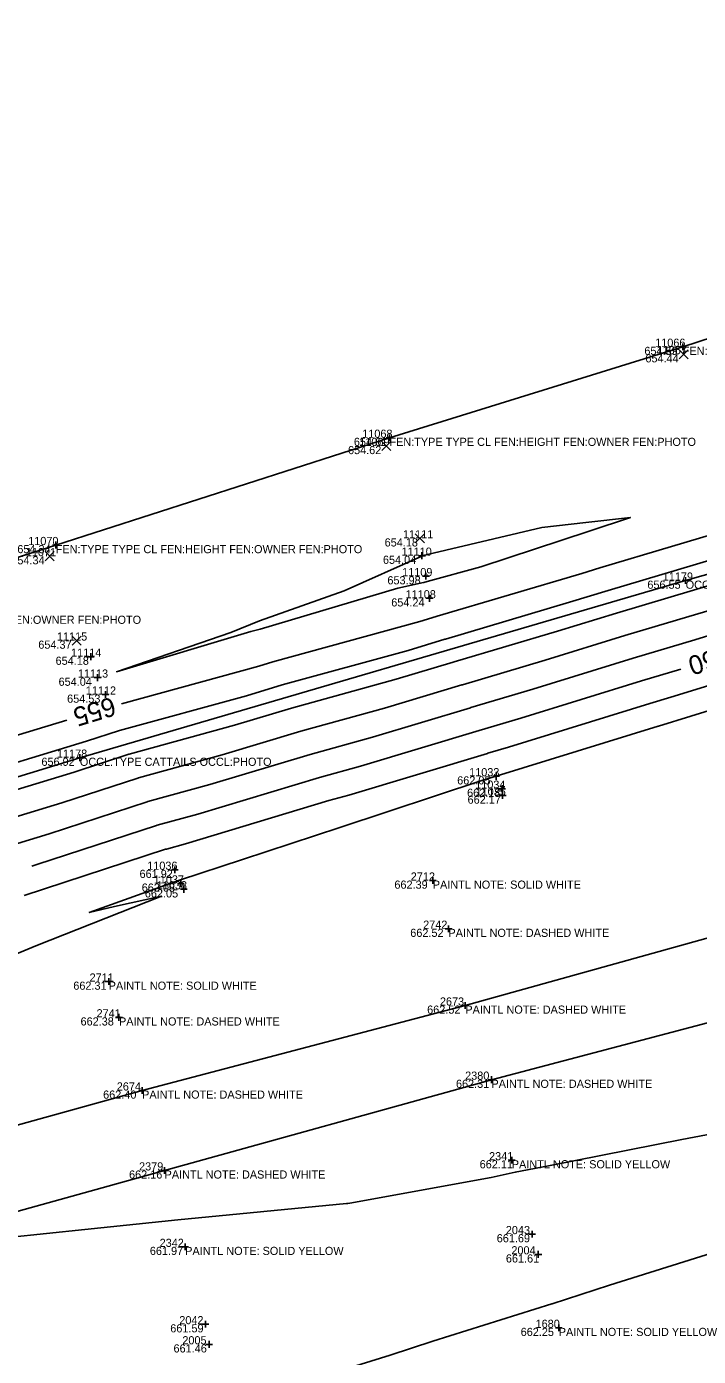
# Model space of a CAD drawing. Extents: x 2129350 to 2137777, y 657588 to 659885.
# Drawn here: x 2130547.1 to 2130646.1, y 657998.8 to 658194.8 of the extents above; entities that cross this region are included whole.
import ezdxf

# ---------------------------------------------------------------- set-up
doc = ezdxf.new("R2010")
doc.units = 0
for name, color, linetype in [('DT_X_Contour_Major', 7, 'Continuous'), ('DT_X_Contour_Minor', 7, 'Continuous'), ('DT_X_TIN_Hull', 7, 'Continuous'), ('PV_X_COP', 7, 'Continuous'), ('SV_X_Occupation_Line', 7, 'Continuous'), ('SV_X_Random_Point', 7, 'Continuous'), ('SV_X_Shot_Marker', 7, 'Continuous'), ('SV_X_Text_Comment', 7, 'Continuous'), ('SV_X_Text_Elevation', 7, 'Continuous'), ('SV_X_Text_Name', 7, 'Continuous')]:
    doc.layers.add(name, color=color, linetype=linetype)

msp = doc.modelspace()

# ---------------------------------------------------------------- linework, layer by layer
at = {"layer": 'DT_X_Contour_Major'}
for points in [[(2130561.04, 658095.02), (2130581.31, 658100.57), (2130583.39, 658101.2), (2130605.06, 658107.14), (2130607.47, 658107.87), (2130607.62, 658107.91), (2130628.95, 658114.23), (2130631.59, 658115.05), (2130652.73, 658121.32), (2130655.56, 658122.19), (2130655.62, 658122.21), (2130657.14, 658122.68)], [(2130643.55, 658100.1), (2130637.73, 658098.38), (2130619.93, 658092.88), (2130613.82, 658091.07), (2130613.78, 658091.06), (2130596.32, 658085.81), (2130590.25, 658084.14), (2130572.3, 658078.74), (2130566.32, 658077.1), (2130566.21, 658077.06), (2130548.57, 658071.3), (2130547.86, 658071.08)], [(2130457.18, 658063.98), (2130465.25, 658066.51), (2130465.52, 658066.59), (2130467.62, 658067.24), (2130489.52, 658073.61), (2130490.94, 658074.05), (2130513.52, 658080.62), (2130513.54, 658080.62), (2130534.28, 658086.89), (2130535.44, 658087.27), (2130553, 658092.59)]]:
    msp.add_lwpolyline(points, dxfattribs=at)
at = {"layer": 'DT_X_Contour_Minor'}
for points in [[(2130539.61, 658076.56), (2130552.24, 658080.39), (2130563.48, 658084.06), (2130563.55, 658084.09), (2130575.91, 658087.47), (2130587.51, 658090.96), (2130599.82, 658094.34), (2130611.26, 658097.78), (2130611.34, 658097.81), (2130623.54, 658101.42), (2130635.28, 658105.05), (2130647.38, 658108.64), (2130659.21, 658112.28), (2130659.48, 658112.37), (2130671.32, 658116.03), (2130682.99, 658119.69), (2130695.3, 658123.5), (2130706.85, 658127.11), (2130708.52, 658127.59), (2130708.94, 658127.73), (2130721.33, 658131.29), (2130732.9, 658134.86), (2130745.25, 658138.41), (2130756.85, 658141.99)], [(2130757.89, 658138.78), (2130743.23, 658134.27), (2130733.96, 658131.6), (2130719.34, 658127.09), (2130710.01, 658124.41), (2130709.48, 658124.24), (2130708.22, 658123.88), (2130693.63, 658119.31), (2130684.36, 658116.44), (2130669.68, 658111.85), (2130660.77, 658109.09), (2130660.42, 658108.98), (2130645.6, 658104.41), (2130636.5, 658101.71), (2130621.73, 658097.15), (2130612.58, 658094.44), (2130612.52, 658094.42), (2130598.07, 658090.07), (2130588.88, 658087.55), (2130574.1, 658083.1), (2130564.93, 658080.59), (2130564.84, 658080.56), (2130550.4, 658075.84), (2130541, 658072.99)], [(2130759.95, 658132.37), (2130739.21, 658125.98), (2130736.06, 658125.08), (2130715.36, 658118.7), (2130712.15, 658117.77), (2130711.39, 658117.54), (2130710.96, 658117.41), (2130690.28, 658110.94), (2130687.1, 658109.96), (2130666.39, 658103.47), (2130663.34, 658102.53), (2130662.86, 658102.38), (2130642.04, 658095.96), (2130638.96, 658095.04), (2130618.13, 658088.61), (2130615.06, 658087.71), (2130615.04, 658087.7), (2130594.57, 658081.54), (2130591.63, 658080.73), (2130570.5, 658074.37), (2130567.7, 658073.6), (2130567.57, 658073.56), (2130546.73, 658066.75)], [(2130605.37, 658116.79), (2130623.03, 658120.97), (2130629.51, 658121.71), (2130636.11, 658122.47), (2130630.03, 658120.46), (2130614.04, 658115.18), (2130606.11, 658113.05), (2130605.62, 658112.9), (2130605.58, 658112.89), (2130601.82, 658112.06), (2130581.5, 658106.02), (2130580.13, 658105.68), (2130560.33, 658099.72), (2130577.18, 658105.53), (2130581.43, 658107.23), (2130593.9, 658111.67), (2130605.36, 658116.78), (2130605.37, 658116.79)], [(2130536.83, 658083.7), (2130555.91, 658089.48), (2130560.75, 658091.07), (2130560.78, 658091.08), (2130579.51, 658096.2), (2130584.77, 658097.79), (2130603.31, 658102.88), (2130608.73, 658104.51), (2130608.86, 658104.54), (2130627.14, 658109.96), (2130632.82, 658111.72), (2130650.95, 658117.09)], [(2130538.22, 658080.13), (2130554.08, 658084.94), (2130562.12, 658087.56), (2130562.17, 658087.58), (2130577.71, 658091.84), (2130586.14, 658094.38), (2130601.56, 658098.61), (2130609.99, 658101.14), (2130610.1, 658101.18), (2130625.34, 658105.69), (2130634.05, 658108.38), (2130649.17, 658112.86)], [(2130544.05, 658057.5), (2130548.44, 658059.32), (2130548.45, 658059.32), (2130566.98, 658066.65), (2130560.03, 658065.12), (2130556.31, 658064.25), (2130569.3, 658068.89), (2130569.33, 658068.9), (2130569.6, 658068.99), (2130578.88, 658072.06), (2130593.26, 658076.75), (2130614.32, 658083.74), (2130616.31, 658084.34), (2130616.31, 658084.34), (2130616.32, 658084.34), (2130640.19, 658091.71), (2130640.26, 658091.73), (2130664.07, 658099.08)], [(2130757.07, 658054.6), (2130734.6, 658048.71), (2130732.06, 658048.2), (2130710.81, 658042.68), (2130706.97, 658041.84), (2130693.16, 658040.01), (2130684.64, 658038.09), (2130668.48, 658035.6), (2130668.37, 658035.57), (2130668.31, 658035.56), (2130653.56, 658032.66), (2130643.7, 658030.81), (2130624.01, 658026.89), (2130619.11, 658025.96), (2130619.09, 658025.96), (2130615.57, 658025.21), (2130594.74, 658021.41), (2130594.43, 658021.38), (2130594.26, 658021.36), (2130569.37, 658018.97), (2130555.65, 658017.51), (2130544.35, 658016.33)], [(2130580.85, 657992.86), (2130600.68, 657999.02), (2130606.99, 658001.08), (2130624.53, 658006.55), (2130624.55, 658006.56), (2130633.04, 658009.32), (2130648.23, 658014.1), (2130659.23, 658017.68), (2130671.97, 658021.7), (2130672.05, 658021.72), (2130684.8, 658025.35), (2130696.04, 658028.73), (2130710.03, 658032.7), (2130720.03, 658035.71), (2130720.11, 658035.73), (2130720.15, 658035.74), (2130736.53, 658041.35), (2130743.88, 658043.65), (2130763.35, 658050.39)]]:
    msp.add_lwpolyline(points, dxfattribs=at)
at = {"layer": 'DT_X_TIN_Hull'}
msp.add_lwpolyline([(2130783.99, 658173.92), (2130725.99, 658174.69), (2130684.1, 658160.72), (2130643.82, 658147.62), (2130600.57, 658134.21), (2130551.36, 658118.4), (2130518.75, 658107.99), (2130476.45, 658094.39), (2130448.2, 658086.06), (2130413.51, 658085.79), (2130380.56, 658076.61), (2130381.83, 658071.95), (2130335.13, 658055.3), (2130245.51, 658030.02)], dxfattribs=at)
at = {"layer": 'PV_X_COP'}
for points in [[(2130756.8, 658090.85), (2130709.64, 658077.1), (2130660.65, 658064.17), (2130611.76, 658050.53), (2130564.1, 658038.01), (2130516.21, 658024.74), (2130467.7, 658011.29), (2130419.56, 657997.56), (2130371.3, 657984.1), (2130323.4, 657971.71), (2130275.02, 657958.65), (2130226.86, 657945.08), (2130178.24, 657931.16), (2130131.49, 657919.16), (2130080.47, 657905.05), (2130033.67, 657891.71)], [(2130037.09, 657880.45), (2130085.21, 657893.8), (2130133.36, 657906.99), (2130181.98, 657920.22), (2130229.94, 657933.91), (2130277.86, 657946.56), (2130326.08, 657959.87), (2130374.09, 657973.32), (2130422.71, 657986.65), (2130470.82, 658000.08), (2130519.45, 658012.91), (2130567.41, 658026.23), (2130615.61, 658039.6), (2130663.49, 658052.2), (2130712.28, 658065.72), (2130760.53, 658079.19)]]:
    msp.add_lwpolyline(points, dxfattribs=at)
at = {"layer": 'SV_X_Occupation_Line'}
msp.add_lwpolyline([(2130087.44, 657957.79), (2130125.12, 657969.49), (2130169.35, 657981.55), (2130211.47, 657989.69), (2130262.21, 658002.55), (2130300.39, 658019.48), (2130344.82, 658026.09), (2130388.98, 658037.78), (2130435.6, 658050.49), (2130554.92, 658087.06), (2130644.25, 658113.16), (2130752.81, 658143.9), (2130803.09, 658157.94), (2130847.96, 658175.12), (2130903.78, 658194.81)], dxfattribs=at)
at = {"layer": 'SV_X_Random_Point'}
for p, q in [((2130643.3, 658145.85), (2130644.63, 658147.19)), ((2130643.3, 658147.19), (2130644.63, 658145.85)), ((2130599.46, 658132.33), (2130600.79, 658133.67)), ((2130599.46, 658133.67), (2130600.79, 658132.33)), ((2130604.38, 658118.72), (2130605.72, 658120.05)), ((2130604.38, 658120.05), (2130605.72, 658118.72)), ((2130549.81, 658116.09), (2130551.14, 658117.43)), ((2130549.81, 658117.43), (2130551.14, 658116.09)), ((2130553.79, 658103.65), (2130555.12, 658104.99)), ((2130553.79, 658104.99), (2130555.12, 658103.65))]:
    msp.add_line(p, q, dxfattribs=at)
at = {"layer": 'SV_X_Shot_Marker'}
for p, q in [((2130643.32, 658147.62), (2130644.32, 658147.62)), ((2130643.82, 658148.12), (2130643.82, 658147.12)), ((2130643.82, 658147.62), (2130643.82, 658147.62)), ((2130600.07, 658134.21), (2130601.07, 658134.21)), ((2130600.57, 658134.71), (2130600.57, 658133.71)), ((2130600.57, 658134.21), (2130600.57, 658134.21)), ((2130550.86, 658118.4), (2130551.86, 658118.4)), ((2130551.36, 658118.9), (2130551.36, 658117.9)), ((2130551.36, 658118.4), (2130551.36, 658118.4)), ((2130605.37, 658117.33), (2130605.37, 658116.33)), ((2130604.87, 658116.83), (2130605.87, 658116.83)), ((2130605.37, 658116.83), (2130605.37, 658116.83)), ((2130605.46, 658113.81), (2130606.46, 658113.81)), ((2130605.96, 658114.31), (2130605.96, 658113.31)), ((2130605.96, 658113.81), (2130605.96, 658113.81)), ((2130644.25, 658113.66), (2130644.25, 658112.66)), ((2130643.75, 658113.16), (2130644.75, 658113.16)), ((2130644.25, 658113.16), (2130644.25, 658113.16)), ((2130605.96, 658110.55), (2130606.96, 658110.55)), ((2130606.46, 658111.05), (2130606.46, 658110.05)), ((2130606.46, 658110.55), (2130606.46, 658110.55)), ((2130556.03, 658101.95), (2130557.03, 658101.95)), ((2130556.53, 658102.45), (2130556.53, 658101.45)), ((2130556.53, 658101.95), (2130556.53, 658101.95)), ((2130557.04, 658098.86), (2130558.04, 658098.86)), ((2130557.54, 658099.36), (2130557.54, 658098.36)), ((2130557.54, 658098.86), (2130557.54, 658098.86)), ((2130558.19, 658096.36), (2130559.19, 658096.36)), ((2130558.69, 658096.86), (2130558.69, 658095.86)), ((2130558.69, 658096.36), (2130558.69, 658096.36)), ((2130554.42, 658087.06), (2130555.42, 658087.06)), ((2130554.92, 658087.56), (2130554.92, 658086.56)), ((2130554.92, 658087.06), (2130554.92, 658087.06)), ((2130615.81, 658084.32), (2130616.81, 658084.32)), ((2130616.31, 658084.82), (2130616.31, 658083.82)), ((2130616.31, 658084.32), (2130616.31, 658084.32)), ((2130616.7, 658082.49), (2130617.7, 658082.49)), ((2130617.2, 658082.99), (2130617.2, 658081.99)), ((2130617.2, 658082.49), (2130617.2, 658082.49)), ((2130616.76, 658081.48), (2130617.76, 658081.48)), ((2130617.26, 658081.98), (2130617.26, 658080.98)), ((2130617.26, 658081.48), (2130617.26, 658081.48)), ((2130568.42, 658070.54), (2130569.42, 658070.54)), ((2130568.92, 658071.04), (2130568.92, 658070.04)), ((2130568.92, 658070.54), (2130568.92, 658070.54)), ((2130569.31, 658068.52), (2130570.31, 658068.52)), ((2130569.81, 658069.02), (2130569.81, 658068.02)), ((2130569.81, 658068.52), (2130569.81, 658068.52)), ((2130606.46, 658068.95), (2130607.46, 658068.95)), ((2130606.96, 658069.45), (2130606.96, 658068.45)), ((2130606.96, 658068.95), (2130606.96, 658068.95)), ((2130569.75, 658067.66), (2130570.75, 658067.66)), ((2130570.25, 658068.16), (2130570.25, 658067.16)), ((2130570.25, 658067.66), (2130570.25, 658067.66)), ((2130608.77, 658061.85), (2130609.77, 658061.85)), ((2130609.27, 658062.35), (2130609.27, 658061.35)), ((2130609.27, 658061.85), (2130609.27, 658061.85)), ((2130558.67, 658054.06), (2130559.67, 658054.06)), ((2130559.17, 658054.56), (2130559.17, 658053.56)), ((2130559.17, 658054.06), (2130559.17, 658054.06)), ((2130611.76, 658051.03), (2130611.76, 658050.03)), ((2130560.19, 658048.79), (2130561.19, 658048.79)), ((2130560.69, 658049.29), (2130560.69, 658048.29)), ((2130560.69, 658048.79), (2130560.69, 658048.79)), ((2130611.26, 658050.53), (2130612.26, 658050.53)), ((2130611.76, 658050.53), (2130611.76, 658050.53)), ((2130615.11, 658039.6), (2130616.11, 658039.6)), ((2130615.61, 658040.1), (2130615.61, 658039.1)), ((2130615.61, 658039.6), (2130615.61, 658039.6)), ((2130563.6, 658038.01), (2130564.6, 658038.01)), ((2130564.1, 658038.51), (2130564.1, 658037.51)), ((2130564.1, 658038.01), (2130564.1, 658038.01)), ((2130618.11, 658027.73), (2130619.11, 658027.73)), ((2130618.61, 658028.23), (2130618.61, 658027.23)), ((2130618.61, 658027.73), (2130618.61, 658027.73)), ((2130566.91, 658026.23), (2130567.91, 658026.23)), ((2130567.41, 658026.73), (2130567.41, 658025.73)), ((2130567.41, 658026.23), (2130567.41, 658026.23)), ((2130570.45, 658015.46), (2130570.45, 658014.46)), ((2130621.1, 658016.84), (2130622.1, 658016.84)), ((2130621.6, 658017.34), (2130621.6, 658016.34)), ((2130621.6, 658016.84), (2130621.6, 658016.84)), ((2130569.95, 658014.96), (2130570.95, 658014.96)), ((2130570.45, 658014.96), (2130570.45, 658014.96)), ((2130622.02, 658013.86), (2130623.02, 658013.86)), ((2130622.52, 658014.36), (2130622.52, 658013.36)), ((2130622.52, 658013.86), (2130622.52, 658013.86)), ((2130573.45, 658004.06), (2130573.45, 658003.06)), ((2130572.95, 658003.56), (2130573.95, 658003.56)), ((2130573.45, 658003.56), (2130573.45, 658003.56)), ((2130625.04, 658003.03), (2130626.04, 658003.03)), ((2130625.54, 658003.53), (2130625.54, 658002.53)), ((2130625.54, 658003.03), (2130625.54, 658003.03)), ((2130573.5, 658000.6), (2130574.5, 658000.6)), ((2130574, 658001.1), (2130574, 658000.1)), ((2130574, 658000.6), (2130574, 658000.6))]:
    msp.add_line(p, q, dxfattribs=at)

# ---------------------------------------------------------------- texts
at = {"layer": 'DT_X_Contour_Major'}
for s, rotation, p in [('660', 197.1269, (2130650.35, 658103.66)), ('655', 196.7996, (2130559.69, 658096.08))]:
    msp.add_text(s, height=2.8, rotation=rotation, dxfattribs=at).set_placement(p)
at = {"layer": 'SV_X_Text_Comment'}
for s, p in [('FEN:TYPE TYPE CL FEN:HEIGHT FEN:OWNER FEN:PHOTO', (2130643.82, 658146.42)), ('FEN:TYPE TYPE CL FEN:HEIGHT FEN:OWNER FEN:PHOTO', (2130600.57, 658133.01)), ('FEN:TYPE TYPE CL FEN:HEIGHT FEN:OWNER FEN:PHOTO', (2130551.36, 658117.2)), ('OCCL:TYPE CATTAILS OCCL:PHOTO', (2130644.25, 658111.96)), ('FEN:TYPE TYPE CL FEN:HEIGHT FEN:OWNER FEN:PHOTO', (2130518.75, 658106.79)), ('OCCL:TYPE CATTAILS OCCL:PHOTO', (2130554.92, 658085.86)), ('PAINTL NOTE: SOLID WHITE', (2130606.96, 658067.75)), ('PAINTL NOTE: DASHED WHITE', (2130609.27, 658060.65)), ('PAINTL NOTE: SOLID WHITE', (2130559.17, 658052.86)), ('PAINTL NOTE: DASHED WHITE', (2130560.69, 658047.59)), ('PAINTL NOTE: DASHED WHITE', (2130611.76, 658049.33)), ('PAINTL NOTE: DASHED WHITE', (2130615.61, 658038.4)), ('PAINTL NOTE: DASHED WHITE', (2130564.1, 658036.81)), ('PAINTL NOTE: SOLID YELLOW', (2130618.61, 658026.54)), ('PAINTL NOTE: DASHED WHITE', (2130567.41, 658025.03)), ('PAINTL NOTE: SOLID YELLOW', (2130570.45, 658013.77)), ('PAINTL NOTE: SOLID YELLOW', (2130625.54, 658001.83))]:
    msp.add_text(s, height=1.2, dxfattribs=at).set_placement(p)
at = {"layer": 'SV_X_Text_Elevation'}
for s, p in [('654.59', (2130638.16, 658146.42)), ('654.44', (2130638.31, 658145.32)), ('654.62', (2130594.46, 658131.8)), ('654.61', (2130595.33, 658133.01)), ('654.18', (2130599.86, 658118.19)), ('654.34', (2130545.7, 658117.2)), ('654.34', (2130544.81, 658115.56)), ('654.04', (2130599.61, 658115.63)), ('653.98', (2130600.27, 658112.61)), ('656.55', (2130638.6, 658111.96)), ('654.24', (2130600.84, 658109.35)), ('654.37', (2130548.79, 658103.12)), ('654.18', (2130551.34, 658100.75)), ('654.04', (2130551.78, 658097.66)), ('654.53', (2130553.04, 658095.16)), ('656.92', (2130549.25, 658085.86)), ('662.05', (2130610.56, 658083.12)), ('662.18', (2130612.02, 658081.29)), ('662.17', (2130612.09, 658080.28)), ('661.92', (2130563.72, 658069.34)), ('662.08', (2130564.04, 658067.32)), ('662.39', (2130601.3, 658067.75)), ('662.05', (2130564.5, 658066.46)), ('662.52', (2130603.64, 658060.65)), ('662.31', (2130553.95, 658052.86)), ('662.38', (2130555.02, 658047.59)), ('662.52', (2130606.13, 658049.33)), ('662.31', (2130610.38, 658038.4)), ('662.40', (2130558.35, 658036.81)), ('662.11', (2130613.87, 658026.54)), ('662.16', (2130562.17, 658025.03)), ('661.69', (2130616.39, 658015.64)), ('661.97', (2130565.24, 658013.77)), ('661.61', (2130617.74, 658012.66)), ('661.59', (2130568.25, 658002.36)), ('662.25', (2130619.92, 658001.83)), ('661.46', (2130568.73, 657999.4))]:
    msp.add_text(s, height=1.2, dxfattribs=at).set_placement(p)
at = {"layer": 'SV_X_Text_Name'}
for s, p in [('11066', (2130639.75, 658147.62)), ('11067', (2130639.97, 658146.52)), ('11068', (2130596.56, 658134.21)), ('11069', (2130596.12, 658133)), ('11070', (2130547.3, 658118.4)), ('11111', (2130602.57, 658119.39)), ('11071', (2130546.95, 658116.76)), ('11110', (2130602.35, 658116.83)), ('11109', (2130602.44, 658113.81)), ('11179', (2130640.87, 658113.16)), ('11108', (2130602.95, 658110.55)), ('11115', (2130551.54, 658104.32)), ('11114', (2130553.62, 658101.95)), ('11113', (2130554.62, 658098.86)), ('11112', (2130555.79, 658096.36)), ('11178', (2130551.54, 658087.06)), ('11033', (2130612.32, 658084.32)), ('11034', (2130613.21, 658082.49)), ('11035', (2130613.26, 658081.48)), ('11036', (2130564.85, 658070.54)), ('11037', (2130565.81, 658068.52)), ('11038', (2130566.25, 658067.66)), ('2712', (2130603.71, 658068.95)), ('2742', (2130605.54, 658061.85)), ('2711', (2130556.35, 658054.06)), ('2673', (2130608.01, 658050.53)), ('2741', (2130557.38, 658048.79)), ('2674', (2130560.36, 658038.01)), ('2380', (2130611.73, 658039.6)), ('2379', (2130563.65, 658026.23)), ('2341', (2130615.26, 658027.73)), ('2043', (2130617.73, 658016.84)), ('2342', (2130566.68, 658014.96)), ('2004', (2130618.55, 658013.86)), ('2042', (2130569.58, 658003.56)), ('1680', (2130622.12, 658003.03)), ('2005', (2130570.03, 658000.6))]:
    msp.add_text(s, height=1.2, dxfattribs=at).set_placement(p)

doc.saveas('drawing.dxf')
